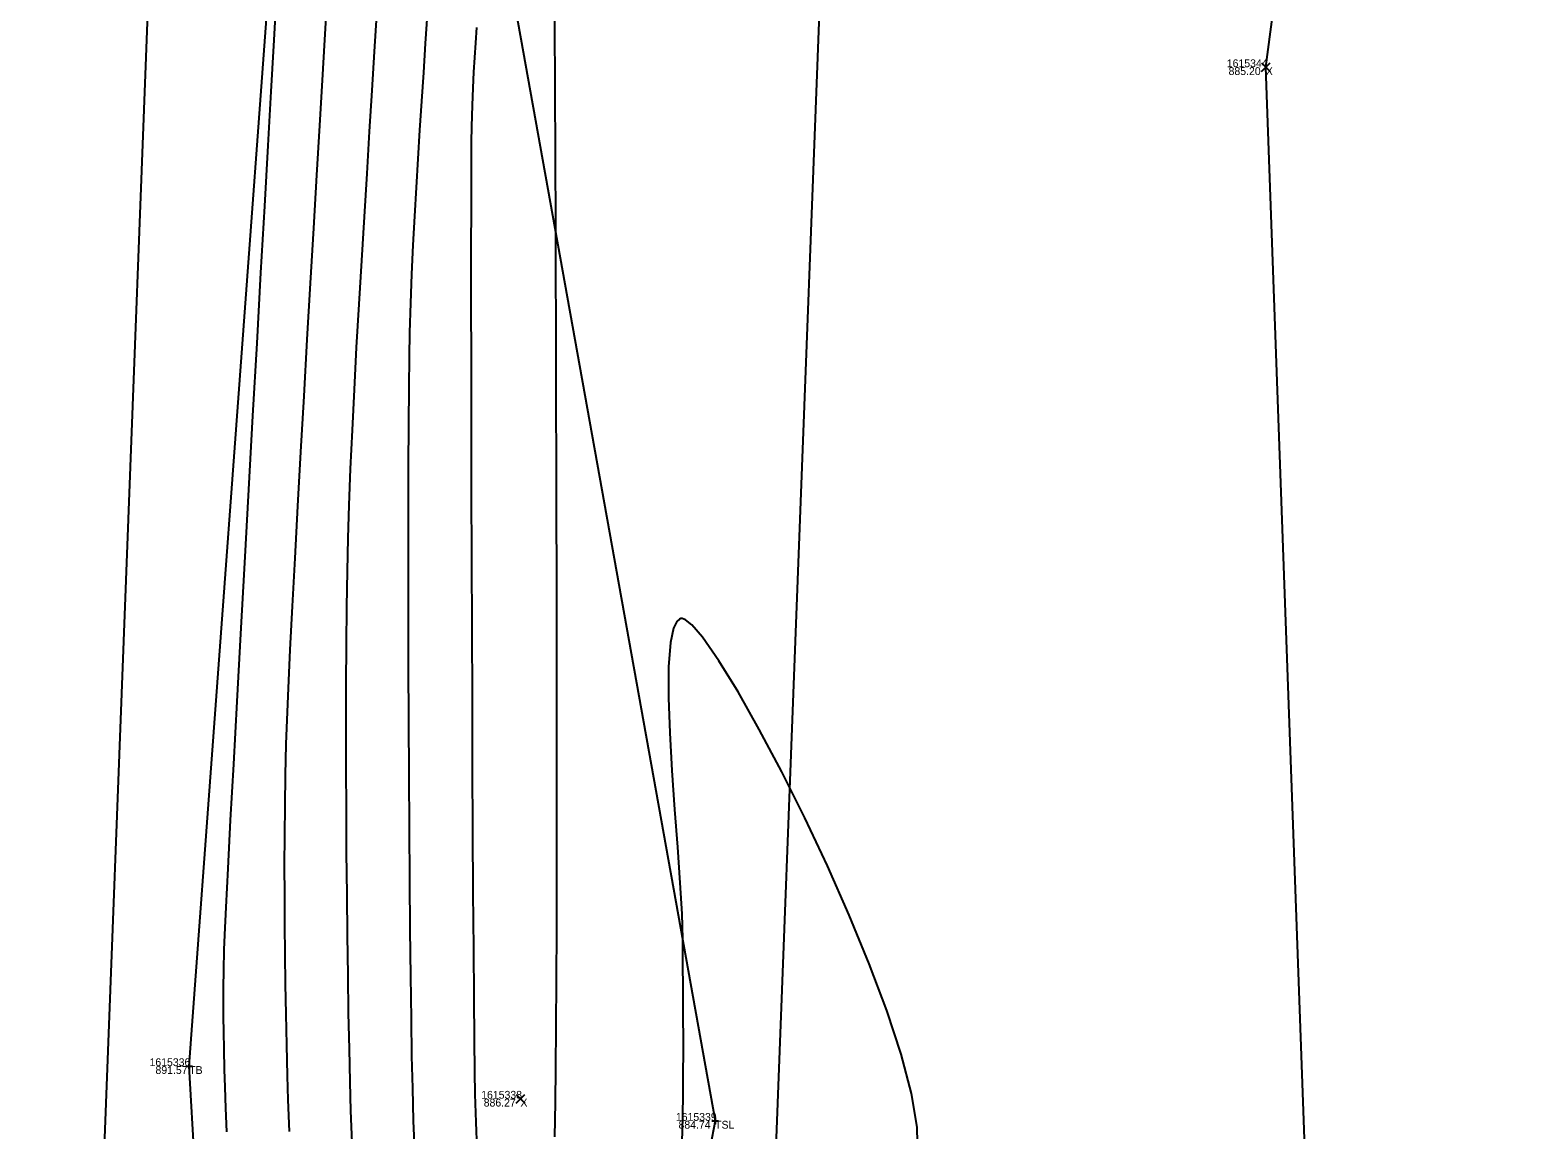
# Model space of a CAD drawing. Extents: x 1957117 to 1971063, y 701601 to 715861.
# Drawn here: x 1962728.9 to 1962796.2, y 702902.1 to 702951.3 of the extents above; entities that cross this region are included whole.
import ezdxf

# ---------------------------------------------------------------- set-up
doc = ezdxf.new("R2010")
doc.units = 0
for name, color, linetype in [('AP_X_Lights', 7, 'Continuous'), ('DT_X_Break_Line', 7, 'Continuous'), ('DT_X_Contour_Major', 7, 'Continuous'), ('DT_X_Contour_Minor', 7, 'Continuous'), ('DT_X_TIN_Hull', 7, 'Continuous'), ('GE_X_CL_20', 7, 'Continuous'), ('PV_P_Drive', 7, 'Continuous'), ('PV_P_Shoulder', 7, 'Continuous'), ('RS_Raster1', 7, 'Continuous'), ('RW_X_Esmt_RR', 7, 'Continuous'), ('SC_Scratch1', 7, 'Continuous')]:
    doc.layers.add(name, color=color, linetype=linetype)

msp = doc.modelspace()

# ---------------------------------------------------------------- linework, layer by layer
at = {"layer": 'AP_X_Lights'}
for p, q in [((1962783.897, 702949.407), (1962784.285, 702949.797)), ((1962783.897, 702949.797), (1962784.285, 702949.407)), ((1962750.601, 702903.306), (1962750.989, 702903.696)), ((1962750.601, 702903.696), (1962750.989, 702903.306))]:
    msp.add_line(p, q, dxfattribs=at)
at = {"layer": 'DT_X_Break_Line'}
for points in [[(1962775.136, 703505.909), (1962781.746, 703450.546), (1962781.126, 703403.871), (1962772.618, 703354.599), (1962766.901, 703307.079), (1962766.998, 703257.586), (1962766.799, 703204.364), (1962764.524, 703155.595), (1962759.673, 703102.271), (1962758.213, 703050.446), (1962755.696, 703003.143), (1962750.431, 702953.017), (1962759.491, 702902.513), (1962750.038, 702852.764), (1962750.74, 702803.015), (1962749.732, 702753.415), (1962752.132, 702702.919), (1962747.065, 702649.147)], [(1962735.623, 702653.941), (1962730.179, 702698.673), (1962732.947, 702753.894), (1962738.207, 702804.216), (1962738.987, 702853.61), (1962736.001, 702904.958), (1962739.593, 702953.751), (1962746.003, 703003.979), (1962748.378, 703053.684), (1962745.135, 703102.004), (1962753.642, 703155.418), (1962750.77, 703204.49), (1962754.665, 703250.528), (1962756.699, 703302.164), (1962759.222, 703352.026), (1962759.063, 703405.067), (1962773.34, 703451.658), (1962770.93, 703504.314)]]:
    msp.add_lwpolyline(points, dxfattribs=at)
at = {"layer": 'DT_X_Contour_Major'}
for points in [[(1962742.133, 702952.359), (1962742.044, 702950.828), (1962741.938, 702949.025), (1962741.818, 702946.993), (1962741.688, 702944.775), (1962741.549, 702942.414), (1962741.406, 702939.953), (1962741.26, 702937.436), (1962741.115, 702934.906), (1962740.973, 702932.405), (1962740.838, 702929.977), (1962740.712, 702927.665), (1962740.598, 702925.512), (1962740.5, 702923.561), (1962740.419, 702921.855), (1962740.359, 702920.438), (1962740.323, 702919.353), (1962740.292, 702917.967), (1962740.27, 702916.604), (1962740.256, 702915.259), (1962740.249, 702913.926), (1962740.25, 702912.602), (1962740.258, 702911.279), (1962740.272, 702909.954), (1962740.291, 702908.622), (1962740.315, 702907.277), (1962740.344, 702905.913), (1962740.376, 702904.527), (1962740.408, 702903.446), (1962740.459, 702902.043)], [(1962742.133, 702952.359), (1962742.044, 702950.828), (1962741.938, 702949.025), (1962741.818, 702946.993), (1962741.688, 702944.775), (1962741.549, 702942.414), (1962741.406, 702939.953), (1962741.26, 702937.436), (1962741.115, 702934.906), (1962740.973, 702932.405), (1962740.838, 702929.977), (1962740.712, 702927.665), (1962740.598, 702925.512), (1962740.5, 702923.561), (1962740.419, 702921.855), (1962740.359, 702920.438), (1962740.323, 702919.353), (1962740.292, 702917.967), (1962740.27, 702916.604), (1962740.256, 702915.259), (1962740.249, 702913.926), (1962740.25, 702912.602), (1962740.258, 702911.279), (1962740.272, 702909.954), (1962740.291, 702908.622), (1962740.315, 702907.277), (1962740.344, 702905.913), (1962740.376, 702904.527), (1962740.408, 702903.446), (1962740.459, 702902.043)], [(1962768.547, 702900.841), (1962768.515, 702902.236), (1962768.264, 702903.73), (1962767.802, 702905.485), (1962767.162, 702907.44), (1962766.378, 702909.535), (1962765.482, 702911.71), (1962764.51, 702913.905), (1962763.493, 702916.06), (1962762.466, 702918.114), (1962761.462, 702920.008), (1962760.515, 702921.681), (1962759.658, 702923.073), (1962758.925, 702924.124), (1962758.45, 702924.679), (1962758.17, 702924.908), (1962758.024, 702924.965), (1962757.964, 702924.962), (1962757.895, 702924.937), (1962757.774, 702924.827), (1962757.628, 702924.525), (1962757.495, 702923.895), (1962757.413, 702922.796), (1962757.408, 702921.422), (1962757.464, 702919.853), (1962757.56, 702918.164), (1962757.681, 702916.433), (1962757.806, 702914.738), (1962757.919, 702913.156), (1962758, 702911.764), (1962758.033, 702910.64), (1962758.034, 702910.409), (1962758.035, 702909.967), (1962758.038, 702909.355), (1962758.042, 702908.617), (1962758.049, 702907.791), (1962758.054, 702907.029), (1962758.058, 702906.29), (1962758.058, 702905.528), (1962758.055, 702904.702), (1962758.046, 702903.766), (1962758.03, 702902.679), (1962757.998, 702901.559)], [(1962768.547, 702900.841), (1962768.515, 702902.236), (1962768.264, 702903.73), (1962767.802, 702905.485), (1962767.162, 702907.44), (1962766.378, 702909.535), (1962765.482, 702911.71), (1962764.51, 702913.905), (1962763.493, 702916.06), (1962762.466, 702918.114), (1962761.462, 702920.008), (1962760.515, 702921.681), (1962759.658, 702923.073), (1962758.925, 702924.124), (1962758.45, 702924.679), (1962758.17, 702924.908), (1962758.024, 702924.965), (1962757.964, 702924.962), (1962757.895, 702924.937), (1962757.774, 702924.827), (1962757.628, 702924.525), (1962757.495, 702923.895), (1962757.413, 702922.796), (1962757.408, 702921.422), (1962757.464, 702919.853), (1962757.56, 702918.164), (1962757.681, 702916.433), (1962757.806, 702914.738), (1962757.919, 702913.156), (1962758, 702911.764), (1962758.033, 702910.64), (1962758.034, 702910.409), (1962758.035, 702909.967), (1962758.038, 702909.355), (1962758.042, 702908.617), (1962758.049, 702907.791), (1962758.054, 702907.029), (1962758.058, 702906.29), (1962758.058, 702905.528), (1962758.055, 702904.702), (1962758.046, 702903.766), (1962758.03, 702902.679), (1962757.998, 702901.559)]]:
    msp.add_lwpolyline(points, dxfattribs=at)
at = {"layer": 'DT_X_Contour_Minor'}
for points in [[(1962737.686, 702902.025), (1962737.64, 702903.08), (1962737.604, 702904.013), (1962737.58, 702904.802), (1962737.558, 702905.722), (1962737.541, 702906.487), (1962737.53, 702907.159), (1962737.525, 702907.799), (1962737.528, 702908.471), (1962737.54, 702909.235), (1962737.561, 702910.155), (1962737.589, 702910.831), (1962737.649, 702912.066), (1962737.738, 702913.792), (1962737.852, 702915.943), (1962737.987, 702918.451), (1962738.14, 702921.251), (1962738.306, 702924.274), (1962738.482, 702927.456), (1962738.663, 702930.727), (1962738.847, 702934.023), (1962739.029, 702937.275), (1962739.205, 702940.418), (1962739.372, 702943.384), (1962739.525, 702946.106), (1962739.661, 702948.518), (1962739.776, 702950.553), (1962739.865, 702952.144)], [(1962737.686, 702902.025), (1962737.64, 702903.08), (1962737.604, 702904.013), (1962737.58, 702904.802), (1962737.558, 702905.722), (1962737.541, 702906.487), (1962737.53, 702907.159), (1962737.525, 702907.799), (1962737.528, 702908.471), (1962737.54, 702909.235), (1962737.561, 702910.155), (1962737.589, 702910.831), (1962737.649, 702912.066), (1962737.738, 702913.792), (1962737.852, 702915.943), (1962737.987, 702918.451), (1962738.14, 702921.251), (1962738.306, 702924.274), (1962738.482, 702927.456), (1962738.663, 702930.727), (1962738.847, 702934.023), (1962739.029, 702937.275), (1962739.205, 702940.418), (1962739.372, 702943.384), (1962739.525, 702946.106), (1962739.661, 702948.518), (1962739.776, 702950.553), (1962739.865, 702952.144)], [(1962744.364, 702951.925), (1962744.266, 702950.297), (1962744.159, 702948.559), (1962744.045, 702946.735), (1962743.928, 702944.845), (1962743.808, 702942.912), (1962743.69, 702940.958), (1962743.575, 702939.005), (1962743.465, 702937.075), (1962743.364, 702935.191), (1962743.272, 702933.375), (1962743.194, 702931.648), (1962743.131, 702930.032), (1962743.085, 702928.551), (1962743.053, 702927.076), (1962743.028, 702925.481), (1962743.011, 702923.786), (1962743, 702922.01), (1962742.996, 702920.174), (1962742.998, 702918.298), (1962743.005, 702916.402), (1962743.017, 702914.505), (1962743.034, 702912.629), (1962743.055, 702910.793), (1962743.08, 702909.017), (1962743.108, 702907.322), (1962743.138, 702905.726), (1962743.172, 702904.252), (1962743.211, 702902.955), (1962743.277, 702901.18)], [(1962744.364, 702951.925), (1962744.266, 702950.297), (1962744.159, 702948.559), (1962744.045, 702946.735), (1962743.928, 702944.845), (1962743.808, 702942.912), (1962743.69, 702940.958), (1962743.575, 702939.005), (1962743.465, 702937.075), (1962743.364, 702935.191), (1962743.272, 702933.375), (1962743.194, 702931.648), (1962743.131, 702930.032), (1962743.085, 702928.551), (1962743.053, 702927.076), (1962743.028, 702925.481), (1962743.011, 702923.786), (1962743, 702922.01), (1962742.996, 702920.174), (1962742.998, 702918.298), (1962743.005, 702916.402), (1962743.017, 702914.505), (1962743.034, 702912.629), (1962743.055, 702910.793), (1962743.08, 702909.017), (1962743.108, 702907.322), (1962743.138, 702905.726), (1962743.172, 702904.252), (1962743.211, 702902.955), (1962743.277, 702901.18)], [(1962746.623, 702951.962), (1962746.542, 702950.662), (1962746.46, 702949.369), (1962746.376, 702948.08), (1962746.293, 702946.795), (1962746.212, 702945.511), (1962746.134, 702944.227), (1962746.061, 702942.941), (1962745.995, 702941.652), (1962745.936, 702940.358), (1962745.886, 702939.057), (1962745.847, 702937.748), (1962745.825, 702936.662), (1962745.808, 702935.28), (1962745.794, 702933.639), (1962745.785, 702931.776), (1962745.78, 702929.727), (1962745.778, 702927.53), (1962745.78, 702925.22), (1962745.786, 702922.834), (1962745.795, 702920.408), (1962745.807, 702917.98), (1962745.822, 702915.586), (1962745.839, 702913.262), (1962745.86, 702911.045), (1962745.883, 702908.971), (1962745.909, 702907.077), (1962745.937, 702905.4), (1962745.967, 702903.976), (1962746.011, 702902.508), (1962746.073, 702900.853)], [(1962746.623, 702951.962), (1962746.542, 702950.662), (1962746.46, 702949.369), (1962746.376, 702948.08), (1962746.293, 702946.795), (1962746.212, 702945.511), (1962746.134, 702944.227), (1962746.061, 702942.941), (1962745.995, 702941.652), (1962745.936, 702940.358), (1962745.886, 702939.057), (1962745.847, 702937.748), (1962745.825, 702936.662), (1962745.808, 702935.28), (1962745.794, 702933.639), (1962745.785, 702931.776), (1962745.78, 702929.727), (1962745.778, 702927.53), (1962745.78, 702925.22), (1962745.786, 702922.834), (1962745.795, 702920.408), (1962745.807, 702917.98), (1962745.822, 702915.586), (1962745.839, 702913.262), (1962745.86, 702911.045), (1962745.883, 702908.971), (1962745.909, 702907.077), (1962745.937, 702905.4), (1962745.967, 702903.976), (1962746.011, 702902.508), (1962746.073, 702900.853)], [(1962752.313, 702951.74), (1962752.319, 702950.611), (1962752.325, 702949.568), (1962752.331, 702948.582), (1962752.337, 702947.624), (1962752.342, 702946.666), (1962752.348, 702945.68), (1962752.352, 702944.637), (1962752.356, 702943.508), (1962752.36, 702942.265), (1962752.362, 702941.341), (1962752.366, 702940.054), (1962752.372, 702938.442), (1962752.378, 702936.549), (1962752.384, 702934.413), (1962752.391, 702932.078), (1962752.397, 702929.582), (1962752.403, 702926.968), (1962752.407, 702924.277), (1962752.411, 702921.549), (1962752.412, 702918.825), (1962752.412, 702916.147), (1962752.409, 702913.555), (1962752.404, 702911.091), (1962752.395, 702908.794), (1962752.383, 702906.707), (1962752.367, 702904.87), (1962752.347, 702903.325), (1962752.315, 702901.791)], [(1962752.313, 702951.74), (1962752.319, 702950.611), (1962752.325, 702949.568), (1962752.331, 702948.582), (1962752.337, 702947.624), (1962752.342, 702946.666), (1962752.348, 702945.68), (1962752.352, 702944.637), (1962752.356, 702943.508), (1962752.36, 702942.265), (1962752.362, 702941.341), (1962752.366, 702940.054), (1962752.372, 702938.442), (1962752.378, 702936.549), (1962752.384, 702934.413), (1962752.391, 702932.078), (1962752.397, 702929.582), (1962752.403, 702926.968), (1962752.407, 702924.277), (1962752.411, 702921.549), (1962752.412, 702918.825), (1962752.412, 702916.147), (1962752.409, 702913.555), (1962752.404, 702911.091), (1962752.395, 702908.794), (1962752.383, 702906.707), (1962752.367, 702904.87), (1962752.347, 702903.325), (1962752.315, 702901.791)], [(1962748.839, 702951.383), (1962748.79, 702950.684), (1962748.746, 702950.033), (1962748.706, 702949.382), (1962748.669, 702948.682), (1962748.637, 702947.886), (1962748.608, 702946.946), (1962748.599, 702946.248), (1962748.592, 702945.057), (1962748.588, 702943.429), (1962748.586, 702941.42), (1962748.587, 702939.086), (1962748.59, 702936.484), (1962748.595, 702933.668), (1962748.602, 702930.696), (1962748.611, 702927.624), (1962748.621, 702924.507), (1962748.633, 702921.401), (1962748.646, 702918.363), (1962748.661, 702915.449), (1962748.676, 702912.715), (1962748.692, 702910.216), (1962748.709, 702908.01), (1962748.727, 702906.151), (1962748.745, 702904.696), (1962748.763, 702903.701), (1962748.8, 702902.45), (1962748.849, 702901.265)], [(1962748.839, 702951.383), (1962748.79, 702950.684), (1962748.746, 702950.033), (1962748.706, 702949.382), (1962748.669, 702948.682), (1962748.637, 702947.886), (1962748.608, 702946.946), (1962748.599, 702946.248), (1962748.592, 702945.057), (1962748.588, 702943.429), (1962748.586, 702941.42), (1962748.587, 702939.086), (1962748.59, 702936.484), (1962748.595, 702933.668), (1962748.602, 702930.696), (1962748.611, 702927.624), (1962748.621, 702924.507), (1962748.633, 702921.401), (1962748.646, 702918.363), (1962748.661, 702915.449), (1962748.676, 702912.715), (1962748.692, 702910.216), (1962748.709, 702908.01), (1962748.727, 702906.151), (1962748.745, 702904.696), (1962748.763, 702903.701), (1962748.8, 702902.45), (1962748.849, 702901.265)]]:
    msp.add_lwpolyline(points, dxfattribs=at)
at = {"layer": 'DT_X_TIN_Hull'}
msp.add_lwpolyline([(1962775.888, 702647.495), (1962778.042, 702697.695), (1962777.816, 702751.499), (1962781.995, 702801.383), (1962785.825, 702901.705), (1962784.091, 702949.602), (1962790.202, 702996.414), (1962788.727, 703101.535), (1962796.63, 703146.099), (1962799.048, 703202.561), (1962802.594, 703299.072), (1962804.686, 703399.836), (1962817.962, 703593.874)], dxfattribs=at)
at = {"layer": 'GE_X_CL_20'}
msp.add_lwpolyline([(1962741.373, 703141.619), (1962697.729, 701998.272)], dxfattribs=at)
at = {"layer": 'PV_P_Drive'}
for p, q in [((1962736.001, 702905.104), (1962736.001, 702904.812)), ((1962735.855, 702904.958), (1962736.147, 702904.958)), ((1962736.001, 702904.958), (1962736.001, 702904.958)), ((1962759.345, 702902.513), (1962759.637, 702902.513)), ((1962759.491, 702902.659), (1962759.491, 702902.367)), ((1962759.491, 702902.513), (1962759.491, 702902.513))]:
    msp.add_line(p, q, dxfattribs=at)
at = {"layer": 'RW_X_Esmt_RR'}
msp.add_lwpolyline([(1962729.176, 702035.621), (1962771.351, 703140.475)], dxfattribs=at)

# ---------------------------------------------------------------- texts
at = {"layer": 'PV_P_Shoulder'}
for s, p in [('885.20', (1962782.427, 702949.252)), ('891.57', (1962734.494, 702904.608)), ('886.27', (1962749.155, 702903.151)), ('884.74', (1962757.857, 702902.163))]:
    msp.add_text(s, height=0.35, dxfattribs=at).set_placement(p)
at = {"layer": 'RS_Raster1'}
for s, p in [('1615344', (1962782.347, 702949.602)), ('1615336', (1962734.229, 702904.958)), ('1615338', (1962749.043, 702903.501)), ('1615339', (1962757.739, 702902.513))]:
    msp.add_text(s, height=0.35, dxfattribs=at).set_placement(p)
at = {"layer": 'SC_Scratch1'}
for s, p in [('X', (1962784.091, 702949.252)), ('TB', (1962736.001, 702904.608)), ('X', (1962750.795, 702903.151)), ('TSL', (1962759.491, 702902.163))]:
    msp.add_text(s, height=0.35, dxfattribs=at).set_placement(p)

doc.saveas('drawing.dxf')
